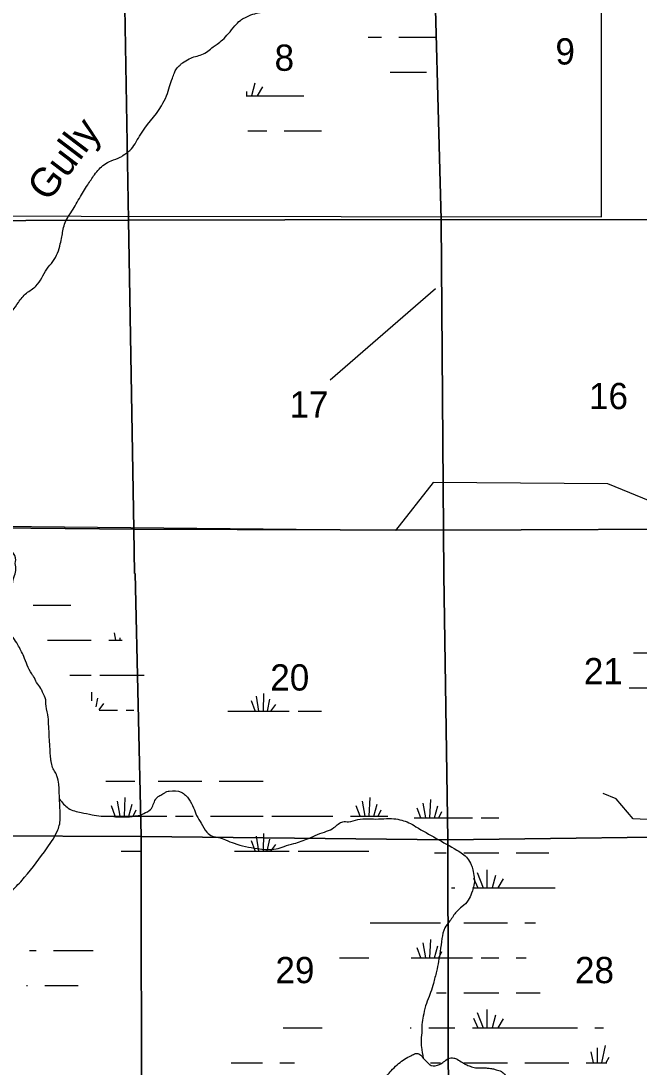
# Model space of a CAD drawing. Extents: x 380424 to 701066, y 1117407 to 1412949.
# Drawn here: x 545820 to 556420, y 1369950 to 1387886 of the extents above; entities that cross this region are included whole.
import ezdxf

# ---------------------------------------------------------------- set-up
doc = ezdxf.new("R2010")
doc.units = 0
for name, color, linetype in [('Cities Incorporated Area', 7, 'Continuous'), ('Local Roads Paved', 7, 'Continuous'), ('Narrow River Creek and Branch and Slough', 7, 'Continuous'), ('Narrow River Creek and Branch and Slough Text', 7, 'Continuous'), ('Section Lines', 7, 'Continuous'), ('Section Numbers', 7, 'Continuous'), ('Swamps', 7, 'Continuous'), ('Wide Rivers and Canals', 7, 'Continuous')]:
    doc.layers.add(name, color=color, linetype=linetype)

msp = doc.modelspace()

# ---------------------------------------------------------------- linework, layer by layer
at = {"layer": 'Cities Incorporated Area'}
for points in [[(528830, 1392097), (528778, 1393430), (530924, 1393406), (530924, 1395182), (531177, 1395181), (531365, 1395181), (535264, 1395165), (535263, 1393991), (539770, 1393991), (539777, 1395156), (542403, 1395155), (542384, 1384546), (555774, 1384527), (555774, 1389875), (554734, 1389890), (554727, 1390413), (553426, 1390420), (552873, 1389914), (552927, 1395153), (572400, 1395149)], [(557462, 1379305), (555882, 1379949), (552889, 1379971), (552245, 1379151), (542588, 1379248), (542530, 1376577), (539389, 1376557), (539389, 1378431), (541008, 1379720), (540969, 1381145), (540267, 1382453), (539395, 1380151), (538128, 1377685), (538127, 1369287)]]:
    msp.add_lwpolyline(points, dxfattribs=at)
at = {"layer": 'Local Roads Paved'}
msp.add_lwpolyline([(559230, 1374430), (558934, 1374557), (558787, 1374565), (558696, 1374557), (557918, 1374270), (557230, 1374090), (557124, 1374122), (556854, 1374213), (556682, 1374188), (556321, 1374204), (556026, 1374549), (555805, 1374639)], dxfattribs=at)
at = {"layer": 'Narrow River Creek and Branch and Slough'}
for points in [[(546537, 1384285), (546569, 1384401), (546622, 1384517), (546675, 1384596), (546822, 1384844), (546965, 1385076), (547081, 1385250), (547250, 1385425), (547366, 1385488), (547524, 1385551), (547614, 1385609), (547688, 1385667), (547852, 1385910), (548232, 1386433), (548316, 1386602), (548369, 1386760), (548416, 1386903), (548453, 1386998), (548485, 1387066), (548548, 1387130), (548591, 1387166), (548707, 1387235), (548812, 1387277), (548923, 1387309), (549119, 1387441), (549187, 1387488), (549277, 1387562), (549377, 1387668), (549488, 1387800), (549583, 1387895), (549662, 1387942), (549799, 1388000), (549921, 1388032), (550011, 1388064), (550100, 1388122), (550195, 1388217), (550269, 1388296), (550343, 1388338), (550459, 1388444), (550523, 1388502), (550602, 1388676), (550681, 1388803), (550744, 1388919), (550797, 1389009), (550866, 1389162), (550950, 1389368), (550998, 1389478), (551077, 1389653), (551103, 1389726), (551204, 1389927), (551251, 1390122), (551299, 1390349), (551325, 1390582), (551388, 1390872), (551399, 1391014), (551383, 1391062), (551378, 1391130), (551394, 1391315), (551394, 1391389), (551388, 1391489), (551383, 1391526), (551372, 1391590), (551346, 1391690), (551325, 1391838), (551314, 1391922), (551309, 1392033), (551299, 1392128), (551299, 1392286), (551288, 1392445), (551299, 1392688), (551299, 1392851), (551320, 1392988), (551341, 1393105), (551367, 1393252), (551404, 1393384), (551431, 1393437), (551457, 1393500), (551489, 1393569), (551515, 1393632), (551531, 1393653), (551547, 1393685), (551584, 1393754), (551621, 1393838), (551636, 1393923), (551663, 1393965), (551684, 1394023), (551710, 1394097), (551730, 1394159)], [(545571, 1372883), (545698, 1373005), (545883, 1373205), (546268, 1373707), (546453, 1374018), (546484, 1374119), (546495, 1374235), (546484, 1374477), (546474, 1374736), (546469, 1374799), (546437, 1374942), (546416, 1374989), (546374, 1375063), (546342, 1375164), (546331, 1375227), (546316, 1375449), (546305, 1375602), (546300, 1375744), (546294, 1375850), (546289, 1375945), (546252, 1376140), (546236, 1376283), (546189, 1376378), (546162, 1376441), (546089, 1376541), (546036, 1376647), (546004, 1376694), (545867, 1376990), (545767, 1377191), (545687, 1377312), (545592, 1377449), (545577, 1377560), (545577, 1377644), (545587, 1377761), (545614, 1377871), (545635, 1377966), (545666, 1378172), (545709, 1378378), (545735, 1378494), (545724, 1378616), (545730, 1378642), (545666, 1378795), (545598, 1378906), (545561, 1378938), (545545, 1378948), (545508, 1378969), (545392, 1379080), (545323, 1379138), (545276, 1379180), (545160, 1379328), (545065, 1379444), (545007, 1379545), (544991, 1379692), (544975, 1379856), (544954, 1379935), (544853, 1380078), (544811, 1380094), (544584, 1380252), (544400, 1380400), (544210, 1380521), (544130, 1380553), (543983, 1380621), (543840, 1380738), (543750, 1380848), (543713, 1380959), (543703, 1381086), (543692, 1381271), (543703, 1381561), (543729, 1381619), (543761, 1381640), (543845, 1381667), (543914, 1381693), (544030, 1381725), (544104, 1381751), (544204, 1381756), (544357, 1381767), (544532, 1381798), (544669, 1381846), (544864, 1381941), (545001, 1382010), (545128, 1382062), (545239, 1382189), (545318, 1382279), (545387, 1382411), (545445, 1382574), (545482, 1382685), (545571, 1382801), (545672, 1382912), (545777, 1383060), (545914, 1383218), (546078, 1383340), (546263, 1383630), (546368, 1383762), (546448, 1383905), (546495, 1384063), (546522, 1384184), (546537, 1384285)], [(546482, 1374544), (546632, 1374388), (546854, 1374314), (547039, 1374277), (547197, 1374251), (547355, 1374251), (547471, 1374240), (547577, 1374240), (547714, 1374245), (547778, 1374256), (547836, 1374261), (547925, 1374298), (548042, 1374367), (548131, 1374541), (548174, 1374588), (548200, 1374604), (548274, 1374646), (548321, 1374673), (548364, 1374683), (548569, 1374662), (548643, 1374609), (548701, 1374541), (548781, 1374393), (548833, 1374261), (548912, 1374129), (549008, 1373976), (549103, 1373907), (549208, 1373886), (549329, 1373844), (549477, 1373786), (549868, 1373696), (550037, 1373680), (550195, 1373691), (550332, 1373733), (550501, 1373781), (550749, 1373870), (550908, 1373939), (551061, 1373992), (551187, 1374055), (551341, 1374156), (551436, 1374156), (551594, 1374192), (551773, 1374208), (551863, 1374203), (552043, 1374208), (552217, 1374208), (552349, 1374182), (552470, 1374140), (552592, 1374071), (553294, 1373670), (553478, 1373527), (553542, 1373417), (553568, 1373332), (553589, 1373205), (553594, 1373179), (553594, 1373105), (553547, 1372931), (553489, 1372810), (553383, 1372699), (553288, 1372614), (553177, 1372456), (553088, 1372335), (553040, 1372155), (553009, 1371933), (552945, 1371590), (552892, 1371384), (552845, 1371231), (552818, 1371157), (552760, 1370999), (552718, 1370820), (552697, 1370682), (552692, 1370535), (552681, 1370382), (552686, 1370292), (552720, 1370102)]]:
    msp.add_spline(points, degree=3, dxfattribs=at)
at = {"layer": 'Section Lines'}
for points in [[(547572, 1389788), (547572, 1389779), (547666, 1384472), (542372, 1384455), (542292, 1389839)], [(552883, 1389777), (553028, 1384482), (547666, 1384472), (547572, 1389779), (547572, 1389788)], [(558230, 1389773), (558354, 1384481), (558354, 1384475), (558342, 1384475), (553028, 1384482), (552883, 1389777), (558225, 1389773)], [(547666, 1384472), (547757, 1379173), (542457, 1379221), (542460, 1379227), (542372, 1384455)], [(553028, 1384482), (553028, 1384466), (553063, 1379154), (547757, 1379173), (547666, 1384472)], [(558354, 1384475), (558368, 1379178), (553073, 1379154), (553063, 1379154), (553028, 1384466), (553028, 1384482), (558342, 1384475)], [(547757, 1379173), (547769, 1378412), (547779, 1378412), (547882, 1373910), (547882, 1373902), (547875, 1373902), (542506, 1373924), (542487, 1378426), (542475, 1378426), (542457, 1379221)], [(553063, 1379154), (553074, 1378397), (553140, 1373844), (547882, 1373902), (547882, 1373910), (547779, 1378412), (547769, 1378412), (547757, 1379173)], [(558368, 1379178), (558381, 1378387), (558414, 1373917), (553140, 1373844), (553074, 1378397), (553063, 1379154), (553073, 1379154)], [(547882, 1373902), (547887, 1368608), (547887, 1368603), (542584, 1368685), (542506, 1373918), (542506, 1373924), (547875, 1373902)], [(553140, 1373844), (553151, 1368591), (553151, 1368582), (547887, 1368603), (547887, 1368608), (547882, 1373902)], [(558414, 1373917), (558449, 1368570), (553151, 1368582), (553151, 1368591), (553140, 1373844)]]:
    msp.add_lwpolyline(points, close=True, dxfattribs=at)
at = {"layer": 'Swamps'}
for p, q in [((552300, 1387610), (552750, 1387610)), ((552150, 1387010), (552750, 1387010)), ((549830, 1386818), (549776, 1386604)), ((549963, 1386758), (549873, 1386604)), ((550336, 1386004), (550786, 1386004)), ((551123, 1381735), (552928, 1383298)), ((546275, 1377271), (546725, 1377271)), ((546725, 1377271), (547025, 1377271)), ((556325, 1377053), (556925, 1377053)), ((546725, 1376671), (547025, 1376671)), ((549899, 1376054), (549860, 1376307)), ((549977, 1376054), (549983, 1376357)), ((556248, 1376453), (556925, 1376453)), ((549837, 1376055), (549771, 1376227)), ((550045, 1376053), (550087, 1376259)), ((550107, 1376053), (550190, 1376167)), ((549671, 1376054), (550421, 1376054)), ((548171, 1374854), (548921, 1374854)), ((549221, 1374854), (549671, 1374854)), ((549671, 1374854), (549971, 1374854)), ((547522, 1374254), (547475, 1374508)), ((547593, 1374254), (547610, 1374570)), ((551722, 1374254), (551675, 1374508)), ((551793, 1374254), (551810, 1374570)), ((552834, 1374223), (552851, 1374539)), ((547437, 1374254), (547371, 1374426)), ((547669, 1374254), (547728, 1374458)), ((547746, 1374254), (547795, 1374362)), ((551637, 1374254), (551571, 1374426)), ((551869, 1374254), (551928, 1374458)), ((551946, 1374254), (551995, 1374362)), ((552763, 1374223), (552717, 1374477)), ((552911, 1374223), (552969, 1374427)), ((552987, 1374223), (553036, 1374332)), ((547271, 1374254), (548321, 1374254)), ((548471, 1374254), (548771, 1374254)), ((549071, 1374254), (549671, 1374254)), ((549671, 1374254), (549971, 1374254)), ((550121, 1374254), (551171, 1374254)), ((553713, 1374223), (554013, 1374223)), ((549977, 1373654), (549983, 1373957)), ((549837, 1373655), (549771, 1373827)), ((549899, 1373654), (549860, 1373907)), ((550044, 1373654), (550087, 1373859)), ((549671, 1373654), (550421, 1373654)), ((550107, 1373653), (550190, 1373767)), ((553413, 1373623), (554013, 1373623)), ((553642, 1373285), (553745, 1373023)), ((553811, 1373334), (553811, 1373023)), ((553956, 1373237), (553903, 1373023)), ((553582, 1373189), (553652, 1373023)), ((554089, 1373177), (553999, 1373023)), ((553563, 1373023), (554913, 1373023)), ((553413, 1372423), (554163, 1372423)), ((552678, 1371823), (552612, 1371995)), ((552763, 1371823), (552717, 1372077)), ((552834, 1371823), (552851, 1372139)), ((552911, 1371823), (552969, 1372027)), ((546381, 1371949), (546831, 1371949)), ((552513, 1371823), (553563, 1371823)), ((552987, 1371823), (553036, 1371932)), ((553713, 1371823), (554013, 1371823)), ((552946, 1371223), (553113, 1371223)), ((553413, 1371223), (554013, 1371223)), ((553811, 1370934), (553811, 1370623)), ((553582, 1370789), (553652, 1370623)), ((553642, 1370885), (553745, 1370623)), ((553956, 1370837), (553903, 1370623)), ((554089, 1370777), (553999, 1370623)), ((550712, 1370623), (550985, 1370623)), ((552812, 1370623), (553262, 1370623)), ((553562, 1370623), (554913, 1370623)), ((554913, 1370623), (555363, 1370623)), ((555595, 1370209), (555632, 1370023)), ((555703, 1370281), (555703, 1370023)), ((555836, 1370318), (555777, 1370023)), ((550262, 1370023), (550513, 1370023)), ((553412, 1370023), (554162, 1370023)), ((554462, 1370023), (554912, 1370023)), ((554912, 1370023), (555213, 1370023))]:
    msp.add_line(p, q, dxfattribs=at)
for points in [[(551776, 1387610), (552000, 1387610)], [(552750, 1387610), (552953, 1387610)], [(552750, 1387010), (552777, 1387010)], [(549684, 1386604), (550669, 1386604)], [(549685, 1386677), (549685, 1386604)], [(549713, 1386004), (550036, 1386004)], [(550786, 1386004), (550972, 1386004)], [(546030, 1377871), (546676, 1377871)], [(547420, 1377392), (547444, 1377271)], [(547325, 1377271), (547558, 1377271)], [(547516, 1377310), (547516, 1377271)], [(546660, 1376671), (546725, 1376671)], [(547175, 1376671), (547931, 1376671)], [(547034, 1376229), (547037, 1376375)], [(547109, 1376125), (547141, 1376277)], [(547161, 1376072), (547244, 1376185)], [(547161, 1376071), (547475, 1376071)], [(547625, 1376071), (547754, 1376071)], [(549368, 1376054), (549671, 1376054)], [(550571, 1376054), (550973, 1376054)], [(547277, 1374854), (547771, 1374854)], [(552678, 1374223), (552614, 1374390)], [(551471, 1374254), (552110, 1374254)], [(552564, 1374223), (553563, 1374223)], [(547539, 1373654), (547871, 1373654)], [(549483, 1373654), (549671, 1373654)], [(550571, 1373654), (551788, 1373654)], [(552910, 1373623), (553113, 1373623)], [(554313, 1373623), (554872, 1373623)], [(553203, 1373023), (553263, 1373023)], [(554913, 1373023), (554981, 1373023)], [(551811, 1372423), (553013, 1372423)], [(554463, 1372423), (554645, 1372423)], [(545966, 1371949), (546081, 1371949)], [(546831, 1371949), (547060, 1371949)], [(551283, 1371823), (551787, 1371823)], [(554313, 1371823), (554482, 1371823)], [(545916, 1371349), (545931, 1371349)], [(546231, 1371349), (546802, 1371349)], [(554313, 1371223), (554725, 1371223)], [(550314, 1370623), (550712, 1370623)], [(552496, 1370623), (552512, 1370623)], [(555663, 1370623), (555807, 1370623)], [(549424, 1370023), (549962, 1370023)], [(552841, 1370023), (553012, 1370023)], [(555513, 1370023), (555868, 1370023)], [(555900, 1370113), (555851, 1370022)]]:
    msp.add_lwpolyline(points, dxfattribs=at)
at = {"layer": 'Wide Rivers and Canals'}
msp.add_spline([(550023, 1367345), (550092, 1367403), (550118, 1367425), (550192, 1367609), (550187, 1367636), (550181, 1367662), (550171, 1367731), (550171, 1367773), (550150, 1367836), (550129, 1367905), (550129, 1367926), (550139, 1368031), (550160, 1368095), (550160, 1368147), (550224, 1368295), (550224, 1368290), (550276, 1368337), (550313, 1368390), (550361, 1368417), (550403, 1368417), (550736, 1368601), (550783, 1368638), (550831, 1368675), (550873, 1368712), (550936, 1368765), (551026, 1368802), (551131, 1368849), (551247, 1368907), (551358, 1368950), (551437, 1369013), (551517, 1369081), (551580, 1369140), (551606, 1369187), (551638, 1369277), (551659, 1369388), (551664, 1369424), (551707, 1369498), (551796, 1369562), (551907, 1369620), (551981, 1369672), (552018, 1369709), (552102, 1369810), (552166, 1369884), (552271, 1369989), (552482, 1370132), (552535, 1370158), (552604, 1370184), (552678, 1370153), (552730, 1370089), (552773, 1370047), (552804, 1370015), (552852, 1369979), (552999, 1369994), (553036, 1370015), (553068, 1370037), (553147, 1370095), (553242, 1370105), (553300, 1370084), (553390, 1370026), (553448, 1369994), (553522, 1369963), (553612, 1369936), (553670, 1369936), (553765, 1369936), (553833, 1369931), (553907, 1369921), (553970, 1369905), (554060, 1369873), (554113, 1369826), (554155, 1369767), (554187, 1369678), (554203, 1369614), (554203, 1369509), (554208, 1369414), (554229, 1369372), (554292, 1369356), (554329, 1369361), (554398, 1369393), (554435, 1369403), (554472, 1369419), (554530, 1369451), (554588, 1369472), (554667, 1369498), (554730, 1369525), (554820, 1369535), (554852, 1369525), (554947, 1369509), (555015, 1369498), (555063, 1369509), (555105, 1369514), (555168, 1369551), (555216, 1369562), (555284, 1369588), (555321, 1369604), (555422, 1369636), (555538, 1369662), (555627, 1369657)], degree=3, dxfattribs=at)

# ---------------------------------------------------------------- texts
at = {"layer": 'Narrow River Creek and Branch and Slough Text'}
msp.add_text('Gully', height=500, rotation=52.7885, dxfattribs=at).set_placement((546288, 1384766))
at = {"layer": 'Section Numbers'}
for s, p in [('9', (554985, 1387139)), ('8', (550169, 1387031)), ('16', (555561, 1381230)), ('17', (550425, 1381085)), ('20', (550095, 1376405)), ('21', (555472, 1376513)), ('29', (550184, 1371388)), ('28', (555320, 1371388))]:
    msp.add_text(s, height=450, dxfattribs=at).set_placement(p)

doc.saveas('drawing.dxf')
